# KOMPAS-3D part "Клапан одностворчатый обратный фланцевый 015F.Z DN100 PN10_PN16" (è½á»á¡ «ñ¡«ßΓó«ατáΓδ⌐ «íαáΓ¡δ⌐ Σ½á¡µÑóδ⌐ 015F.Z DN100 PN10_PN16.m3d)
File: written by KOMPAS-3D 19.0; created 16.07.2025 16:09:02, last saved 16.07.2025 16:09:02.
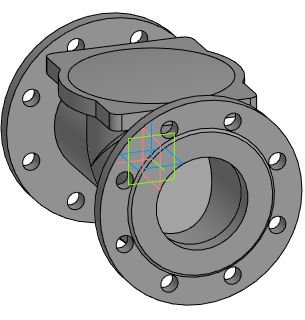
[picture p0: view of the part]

Document properties: Полное имя файла: E:\Dendor Работа Сачек\3D для проектировщиков\5.4 Тип 015F.Z. Клапан одностворчатый обратный фланцевый\stp_Клапан одностворчатый обратный фланцевый 015F.Z PN10_16\Клапан одностворчатый обратный фланцевый 015F.Z DN100 PN10_PN16.m3d

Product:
- Part/product: Клапан одностворчатый обратный фланцевый 015F.Z DN100 PN10_PN16

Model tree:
1. Операция без истории:1
2. Операция без истории:2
